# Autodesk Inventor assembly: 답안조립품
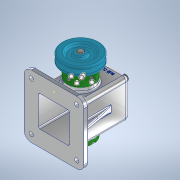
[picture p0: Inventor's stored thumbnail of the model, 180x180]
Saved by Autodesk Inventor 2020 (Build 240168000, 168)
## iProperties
Created: 2022-11
Part Number: 답안조립품
Document SubType Name: Assembly
Designer: USER
Author: USER
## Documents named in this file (16)
- C:\Users\USER\Desktop\721106V1018\답안조립품.iam
- C:\Users\USER\Desktop\721106V1018\본체.ipt.ipt
- C:\Users\USER\Desktop\721106V1018\부시.ipt
- C:\Users\USER\Desktop\721106V1018\편심축.ipt
- C:\Users\USER\Desktop\721106V1018\베어링 6201.ipt
- C:\Users\USER\Desktop\721106V1018\뒤커버.ipt
- C:\Users\USER\Desktop\721106V1018\앞커버.ipt
- C:\Users\USER\Desktop\721106V1018\볼트 M4 x 12.ipt
- C:\Users\USER\Desktop\721106V1018\링크.ipt
- C:\Users\USER\Desktop\721106V1018\슬라이드.ipt
- C:\Users\USER\Desktop\721106V1018\핀 5 x 18.ipt
- C:\Users\USER\Desktop\721106V1018\고정핀 1.2 x 10.ipt
- C:\Users\USER\Desktop\721106V1018\오일실 12 25 7.ipt
- C:\Users\USER\Desktop\721106V1018\키 4 x 4 x 15.ipt
- C:\Users\USER\Desktop\721106V1018\V벨트풀리.ipt
- 본체.ipt
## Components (11 placed, 4 different names)
1. ISO 4762 M4 x 12:1
2. ISO 4762 M4 x 12:2
3. ISO 4762 M4 x 12:3
4. ISO 4762 M4 x 12:4
5. ISO 4762 M4 x 12:5
6. ISO 4762 M4 x 12:6
7. ISO 4762 M4 x 12:7
8. ISO 4762 M4 x 12:8
9. 핀 5 x 18:1
10. 고정핀 1.2 x 10:1
11. V벨트풀리:1
